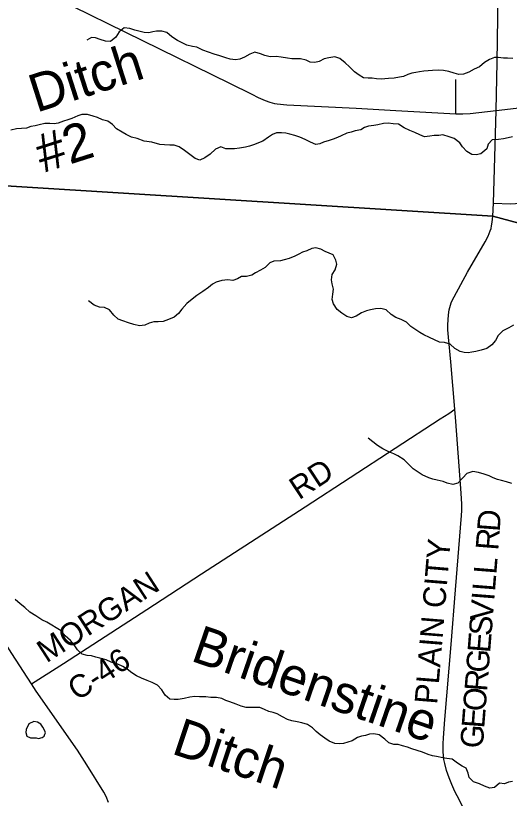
# Model space of a CAD drawing. Extents: x 114604 to 551442, y 316898 to 567001.
# Drawn here: x 126312 to 132822, y 394917 to 405241 of the extents above; entities that cross this region are included whole.
import ezdxf

# ---------------------------------------------------------------- set-up
doc = ezdxf.new("R2010")
doc.units = 0
for name, color, linetype in [('GE_P_Alignment_1000_Cardinal_Points', 7, 'Continuous'), ('GE_P_Alignment_500_Bearings', 7, 'Continuous'), ('GE_P_Alignment_500_Distances', 7, 'Continuous'), ('MT_X_Edge_Line', 7, 'Continuous'), ('PM_P_Cells', 7, 'Continuous'), ('PM_P_CL_Double_Solid', 7, 'Continuous'), ('PM_P_Stop_Line', 7, 'Continuous')]:
    doc.layers.add(name, color=color, linetype=linetype)

msp = doc.modelspace()

# ---------------------------------------------------------------- linework, layer by layer
at = {"layer": 'GE_P_Alignment_1000_Cardinal_Points'}
msp.add_line((132116, 403946), (132118, 404397), dxfattribs=at)
msp.add_lwpolyline([(132612, 402769), (132838, 402760), (132904, 402761), (132968, 402766), (133000, 402771), (133063, 402789), (133093, 402800), (133122, 402813), (133150, 402829), (133178, 402846), (133227, 402883), (133252, 402906), (133364, 403022), (133410, 403067), (133434, 403088), (133594, 403197), (133644, 403236), (133667, 403259), (133706, 403306), (133741, 403356), (133814, 403490), (133846, 403542), (133864, 403567)], dxfattribs=at)
at = {"layer": 'GE_P_Alignment_500_Bearings'}
msp.add_line((132604, 402595), (132612, 402769), dxfattribs=at)
for points in [[(132646, 403991), (132661, 404629), (132671, 405218), (132683, 406508)], [(126839, 405479), (129131, 404352), (129424, 404207), (129511, 404161), (129601, 404120), (129662, 404099), (129726, 404083), (129758, 404077), (129889, 404066), (130803, 404021), (131326, 403989), (132116, 403946)], [(132646, 403991), (133251, 404061), (133674, 404107), (134642, 404218), (135381, 404299)], [(132116, 403946), (132208, 403946), (132307, 403951), (132646, 403991)], [(132612, 402769), (132624, 403220), (132646, 403991)], [(132102, 400048), (132050, 400676), (132019, 401000), (132012, 401098), (132011, 401163), (132014, 401229), (132019, 401294), (132028, 401359), (132044, 401423), (132054, 401454), (132067, 401484), (132092, 401534), (132272, 401858), (132501, 402256), (132541, 402334), (132571, 402404), (132581, 402435), (132588, 402467), (132596, 402516), (132604, 402595)], [(126519, 396426), (126262, 396828), (126090, 397091), (125336, 398220), (124956, 398794), (124886, 398905), (124855, 398962), (124821, 399032), (124730, 399230), (124642, 399428), (124322, 400169)], [(126519, 396426), (126942, 396697), (128042, 397407), (128764, 397878), (130129, 398761), (131911, 399923), (132022, 399994), (132102, 400048)], [(132420, 394396), (132135, 394950), (132105, 395009), (132064, 395098), (132027, 395189), (131995, 395286), (131969, 395377), (131959, 395427), (131954, 395474), (131950, 395540), (131950, 395638), (131954, 395717), (131971, 395958), (132054, 396946), (132110, 397666), (132190, 398646), (132194, 398712), (132195, 398799), (132188, 398941), (132158, 399300), (132115, 399889), (132102, 400048)], [(127535, 394861), (127505, 394940), (127475, 394998), (127250, 395360), (127127, 395553), (126582, 396332), (126519, 396426)]]:
    msp.add_lwpolyline(points, dxfattribs=at)
at = {"layer": 'GE_P_Alignment_500_Distances'}
for points in [[(122791, 403209), (132603, 402598), (133453, 402366)], [(133453, 402366), (132603, 402598), (122791, 403209)]]:
    msp.add_lwpolyline(points, dxfattribs=at)
at = {"layer": 'MT_X_Edge_Line'}
for points in [[(126696, 395763), (126704, 395781), (126698, 395809), (126670, 395855), (126646, 395895), (126600, 395923), (126552, 395929), (126484, 395900)], [(126484, 395900), (126452, 395827), (126446, 395785), (126458, 395735), (126506, 395713), (126556, 395717), (126582, 395713), (126614, 395707), (126660, 395719), (126686, 395739), (126696, 395763)]]:
    msp.add_lwpolyline(points, dxfattribs=at)
at = {"layer": 'PM_P_Cells'}
for points in [[(127885, 405048), (127819, 405071), (127743, 405081), (127679, 405027), (127634, 404957), (127564, 404901), (127498, 404906), (127428, 404926), (127364, 404948), (127314, 404952), (127252, 404916)], [(132866, 404674), (132798, 404682), (132745, 404682), (132675, 404687), (132625, 404687), (132561, 404663), (132493, 404623), (132426, 404567), (132358, 404535), (132288, 404496), (132218, 404468), (132156, 404466), (132092, 404480), (132024, 404505), (131952, 404517), (131885, 404521), (131809, 404517), (131751, 404513), (131693, 404508), (131639, 404498), (131589, 404490), (131537, 404484), (131485, 404464), (131424, 404440), (131374, 404429), (131304, 404415), (131230, 404411), (131180, 404409), (131130, 404403), (131068, 404408), (131012, 404414), (130960, 404418), (130897, 404422), (130842, 404457), (130782, 404499), (130712, 404565), (130658, 404620), (130588, 404676), (130522, 404698), (130442, 404685), (130382, 404669), (130315, 404637), (130257, 404621), (130197, 404629), (130141, 404652), (130067, 404672), (130009, 404670), (129955, 404672), (129897, 404678), (129815, 404693), (129745, 404701), (129669, 404697), (129599, 404716), (129541, 404738), (129465, 404758), (129400, 404734), (129330, 404695), (129270, 404667), (129210, 404657), (129140, 404665), (129084, 404685), (129002, 404712), (128930, 404734), (128778, 404787), (128702, 404823), (128642, 404835), (128570, 404850), (128500, 404886), (128448, 404914), (128372, 404963), (128306, 405019), (128240, 405035), (128170, 405037), (128120, 405026), (128069, 405016), (128005, 405020), (127953, 405030), (127885, 405048)], [(129817, 403694), (129751, 403693), (129698, 403673), (129648, 403639), (129570, 403583), (129514, 403561), (129460, 403541), (129395, 403519), (129341, 403504), (129265, 403492), (129197, 403486), (129147, 403482), (129083, 403486), (129017, 403509), (128946, 403481), (128878, 403413), (128806, 403365), (128742, 403333), (128680, 403356), (128608, 403408), (128538, 403462), (128470, 403509), (128400, 403531), (128346, 403533), (128274, 403535), (128214, 403542), (128106, 403574), (128005, 403587), (127915, 403619), (127839, 403637), (127767, 403674), (127715, 403702), (127643, 403748), (127590, 403805), (127526, 403849), (127458, 403867), (127390, 403897), (127332, 403916), (127258, 403938), (127184, 403938), (127133, 403920), (127053, 403885), (127001, 403865), (126941, 403847), (126871, 403823), (126818, 403813), (126764, 403818), (126696, 403816), (126624, 403802), (126568, 403788), (126510, 403778), (126454, 403758), (126390, 403753), (126321, 403747), (126247, 403731)], [(132865, 403643), (132807, 403630), (132743, 403618), (132677, 403608), (132595, 403602), (132544, 403546), (132524, 403486), (132446, 403420), (132384, 403405), (132328, 403409), (132262, 403447), (132206, 403511), (132170, 403562), (132096, 403620), (132026, 403644), (131944, 403667), (131890, 403661), (131832, 403659), (131772, 403649), (131704, 403642), (131640, 403668), (131576, 403698), (131508, 403728), (131436, 403763), (131360, 403809), (131288, 403813), (131223, 403822), (131161, 403818), (131089, 403800), (131033, 403790), (130963, 403783), (130913, 403767), (130863, 403735), (130790, 403723), (130736, 403705), (130680, 403689), (130606, 403655), (130554, 403634), (130499, 403612), (130445, 403594), (130373, 403572), (130321, 403548), (130269, 403542), (130201, 403571), (130129, 403607), (130061, 403637), (129993, 403658), (129927, 403678), (129875, 403692), (129817, 403694)], [(132875, 401157), (132813, 401124), (132737, 401082), (132676, 401020), (132638, 400956), (132590, 400900), (132523, 400852), (132451, 400828), (132381, 400812), (132327, 400800), (132277, 400793), (132227, 400799), (132173, 400809), (132105, 400851), (132043, 400908), (131967, 400928), (131899, 400936), (131835, 400963), (131767, 400995), (131695, 401031), (131643, 401060), (131587, 401098), (131523, 401142), (131467, 401199), (131397, 401235), (131325, 401259), (131263, 401297), (131199, 401360), (131127, 401376), (131057, 401372), (130993, 401361), (130939, 401349), (130873, 401319), (130804, 401277), (130740, 401257), (130678, 401273), (130614, 401316), (130550, 401366), (130502, 401439), (130487, 401495), (130495, 401569), (130505, 401635), (130484, 401705), (130476, 401755), (130484, 401828), (130524, 401888), (130547, 401964), (130533, 402016), (130497, 402084), (130445, 402110), (130393, 402129), (130337, 402161), (130271, 402179), (130219, 402169), (130153, 402139), (130095, 402120), (130044, 402096), (129992, 402070), (129918, 402038), (129854, 402020), (129802, 402008), (129716, 402001), (129665, 401981), (129603, 401919), (129539, 401885), (129475, 401847), (129424, 401817), (129358, 401801), (129290, 401798), (129236, 401770), (129174, 401746), (129108, 401754), (129031, 401746), (128957, 401727), (128907, 401699), (128855, 401657), (128782, 401603), (128702, 401549), (128638, 401499), (128567, 401443), (128501, 401371), (128457, 401313), (128402, 401262), (128328, 401232), (128258, 401208), (128192, 401202), (128136, 401204), (128072, 401185), (128017, 401159), (127947, 401149), (127871, 401165), (127799, 401187), (127727, 401216), (127663, 401238), (127605, 401288), (127551, 401359), (127485, 401389), (127417, 401397)], [(127417, 401397), (127345, 401424), (127271, 401478)], [(132856, 399068), (132786, 399092), (132718, 399108), (132666, 399122), (132608, 399144), (132555, 399170), (132489, 399194), (132415, 399214), (132341, 399226), (132261, 399202), (132209, 399146), (132143, 399076), (132075, 399058), (132003, 399074), (131947, 399096), (131869, 399114), (131811, 399128), (131759, 399143), (131671, 399185), (131619, 399219), (131553, 399263), (131489, 399331), (131437, 399383), (131353, 399435), (131299, 399461), (131233, 399487), (131154, 399529), (131084, 399569), (131022, 399619), (130960, 399666)], [(130024, 395926), (129952, 395940), (129896, 395958), (129832, 395992), (129758, 396033), (129706, 396049), (129650, 396063), (129592, 396087), (129530, 396115), (129476, 396117), (129416, 396113), (129352, 396117), (129284, 396133), (129219, 396157), (129137, 396189), (129085, 396207), (129029, 396233), (128959, 396245), (128887, 396249), (128819, 396255), (128735, 396257), (128675, 396259), (128609, 396251), (128533, 396235), (128455, 396219), (128403, 396221), (128345, 396225), (128283, 396277), (128239, 396346), (128181, 396410), (128113, 396444), (128047, 396472), (127971, 396502), (127904, 396534), (127842, 396574), (127784, 396620), (127726, 396658), (127660, 396688), (127572, 396712), (127504, 396742), (127424, 396764), (127368, 396778), (127314, 396797), (127256, 396799), (127190, 396817), (127126, 396877), (127084, 396941), (127034, 396997), (126966, 397061), (126914, 397127), (126845, 397165), (126789, 397201), (126723, 397239), (126657, 397271), (126579, 397322), (126501, 397374), (126431, 397432), (126373, 397482), (126307, 397540)], [(132864, 395138), (132812, 395130), (132756, 395110), (132692, 395116), (132628, 395058), (132566, 395050), (132494, 395078), (132426, 395108), (132348, 395136), (132294, 395190), (132280, 395247), (132254, 395313), (132200, 395343), (132140, 395381), (132068, 395435), (131997, 395443), (131945, 395451), (131861, 395467), (131807, 395477), (131751, 395495), (131675, 395527), (131605, 395549), (131535, 395571), (131479, 395593), (131411, 395611), (131357, 395629), (131297, 395627), (131233, 395651), (131179, 395698), (131105, 395754), (131033, 395768), (130979, 395764), (130923, 395746), (130871, 395736), (130819, 395718), (130751, 395676), (130691, 395656), (130633, 395642), (130579, 395636), (130519, 395642), (130446, 395670), (130388, 395710), (130328, 395754), (130274, 395798), (130226, 395848), (130162, 395892), (130086, 395914), (130024, 395926)]]:
    msp.add_lwpolyline(points, dxfattribs=at)

# ---------------------------------------------------------------- texts
at = {"layer": 'PM_P_CL_Double_Solid'}
for s, rotation, p in [('RD', 33.294, (130049, 398847)), ('D', 85.7775, (132694, 398428)), ('R', 85.5189, (132675, 398181)), ('PLAIN CITY', 85.3182, (131870, 396150)), ('L', 85.4968, (132650, 397865)), ('MORGAN', 32.9045, (126719, 396696)), ('L', 85.4856, (132632, 397641)), ('I', 85.4878, (132622, 397518)), ('V', 85.4882, (132602, 397255)), ('S', 85.4829, (132586, 397053)), ('E', 85.4856, (132568, 396829)), ('C-46', 32.9609, (127124, 396195)), ('G', 85.4862, (132547, 396566)), ('R', 85.4839, (132528, 396320)), ('O', 85.506, (132507, 396057)), ('E', 85.5803, (132490, 395834)), ('G', 86.3939, (132473, 395571))]:
    msp.add_text(s, height=300, rotation=rotation, dxfattribs=at).set_placement(p)
at = {"layer": 'PM_P_Stop_Line'}
for s, height, rotation, p in [('Ditch', 500, 17.7004, (126586, 403959)), ('#2', 500, 17.7004, (126670, 403163)), ('Bridenstine', 500.01, 340.9829, (128605, 396736)), ('Ditch', 500, 341.5976, (128352, 395511))]:
    msp.add_text(s, height=height, rotation=rotation, dxfattribs=at).set_placement(p)

doc.saveas('drawing.dxf')
